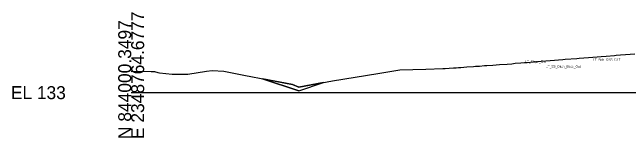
# Model space of a CAD drawing. Extents: x -26 to 2349090, y -10 to 844481.
# Drawn here: x 974.3 to 1107.5, y 15990.3 to 16017.3 of the extents above; entities that cross this region are included whole.
import ezdxf

# ---------------------------------------------------------------- set-up
doc = ezdxf.new("R2010")
doc.units = 0
for name, color, linetype in [('Exist Cross Section Cell', 7, 'Continuous'), ('Exist XS Ground Line', 7, 'Continuous'), ('Prop CMT Ditch DDE', 7, 'Continuous'), ('Prop Road Sect_ Recs - UUC (Outline)', 7, 'Continuous'), ('Scratch_Level_0', 7, 'Continuous')]:
    doc.layers.add(name, color=color, linetype=linetype)

msp = doc.modelspace()

# ---------------------------------------------------------------- linework, layer by layer
at = {"layer": 'Exist Cross Section Cell'}
msp.add_line((1000, 16000), (1150, 16000), dxfattribs=at)
at = {"layer": 'Exist XS Ground Line'}
msp.add_lwpolyline([(1000, 16004.55), (1002.72, 16004.6), (1004.34, 16004.53), (1005.04, 16004.52), (1005.73, 16004.37), (1006.13, 16004.3), (1008.86, 16003.97), (1009.65, 16003.99), (1012.24, 16003.98), (1016.26, 16004.62), (1017.53, 16004.75), (1020.02, 16004.66), (1024.36, 16003.77), (1034.83, 16001.77), (1036.21, 16001.18), (1043.53, 16002.54), (1053.3, 16004.15), (1058.1, 16004.95), (1063.68, 16005.09), (1067.39, 16005.19), (1067.87, 16005.21), (1068.71, 16005.25), (1069.7, 16005.33), (1070.27, 16005.38), (1070.73, 16005.41), (1071.26, 16005.42), (1072.54, 16005.53), (1074, 16005.64), (1074.41, 16005.67), (1075.27, 16005.74), (1076.35, 16005.82), (1076.85, 16005.86), (1078.14, 16005.95), (1079.59, 16006.05), (1081.28, 16006.17), (1082.24, 16006.24), (1083.03, 16006.32), (1084.23, 16006.41), (1085, 16006.46), (1085.62, 16006.52), (1086.97, 16006.63), (1087.83, 16006.71), (1088.59, 16006.77), (1090.55, 16006.92), (1093.29, 16007.14), (1093.8, 16007.18), (1096.32, 16007.38), (1096.8, 16007.43), (1098.88, 16007.57), (1100.7, 16007.72), (1101.6, 16007.8), (1102.68, 16007.89), (1104.47, 16008.02), (1104.8, 16008.04), (1105.75, 16008.13), (1106.86, 16008.21), (1108.86, 16008.37)], dxfattribs=at)
at = {"layer": 'Prop CMT Ditch DDE'}
for q in [(1028.4, 16003), (1041.55, 16002.17)]:
    msp.add_line((1036.21, 16000.39), q, dxfattribs=at)
at = {"layer": 'Prop Road Sect_ Recs - UUC (Outline)'}
msp.add_lwpolyline([(1028.4, 16003), (1036.21, 16000.39), (1041.55, 16002.17), (1036.21, 16001.18), (1034.83, 16001.77)], close=True, dxfattribs=at)

# ---------------------------------------------------------------- texts
at = {"layer": 'Exist Cross Section Cell'}
for s, p in [('E 2348764.6777', (1002.8, 15990)), ('N 844000.3497', (1000, 15990))]:
    msp.add_text(s, height=2.8, rotation=90, dxfattribs=at).set_placement(p)
msp.add_text('EL 133', height=2.8, dxfattribs=at).set_placement((974, 15998.6))
at = {"layer": 'Scratch_Level_0'}
for s, p in [('LT_Slope_Cut', (1085.17, 16006.45)), ('LT_Sub_OSS_DLT', (1099.79, 16006.86)), ('LT_SS_Ditch_Base_Out', (1089.64, 16005.39))]:
    msp.add_text(s, height=0.5, dxfattribs=at).set_placement(p)

doc.saveas('drawing.dxf')
